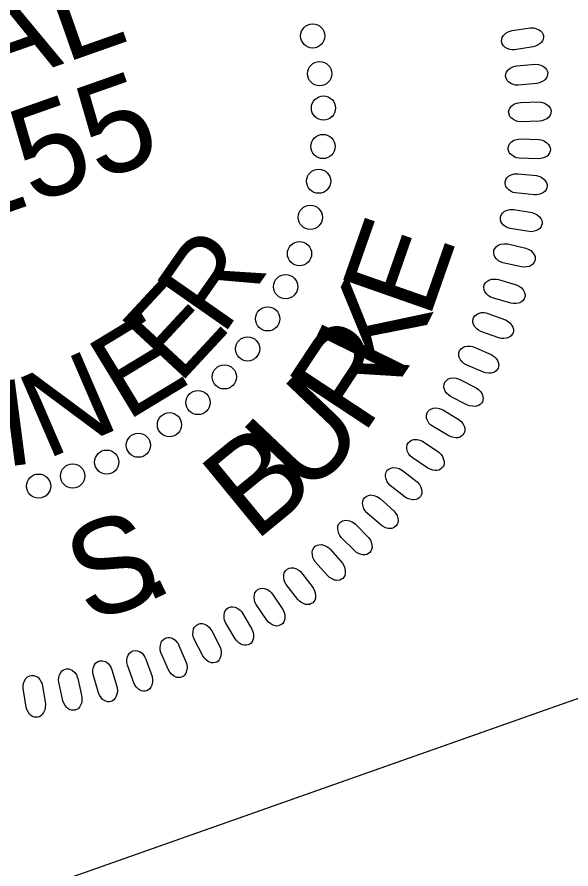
# Model space of a CAD drawing. Extents: x 473817 to 475769, y 501102 to 502694.
# Drawn here: x 475387 to 475423.7, y 502506.6 to 502563 of the extents above; entities that cross this region are included whole.
import ezdxf

# ---------------------------------------------------------------- set-up
doc = ezdxf.new("R2010")
doc.units = 0
for name, color, linetype in [('Sheet PE Seal Cell', 7, 'Continuous'), ('Sheet Plan CELL', 7, 'Continuous'), ('Sheet Sticker Exception Certification CELL', 7, 'Continuous'), ('Sheet Sticker Incomplete CELL', 7, 'Continuous')]:
    doc.layers.add(name, color=color, linetype=linetype)

msp = doc.modelspace()

# ---------------------------------------------------------------- linework, layer by layer
at = {"layer": 'Sheet PE Seal Cell'}
for points in [[(475419.758, 502562.096), (475420.971, 502562.279), (475421.193, 502562.275), (475421.339, 502562.245), (475421.524, 502562.159), (475421.647, 502562.079), (475421.742, 502561.981), (475421.797, 502561.883), (475421.834, 502561.775), (475421.831, 502561.662), (475421.819, 502561.539), (475421.776, 502561.426), (475421.692, 502561.308), (475421.623, 502561.237), (475421.485, 502561.148), (475421.316, 502561.062), (475421.162, 502561.016), (475419.921, 502560.82), (475419.75, 502560.817), (475419.605, 502560.841), (475419.434, 502560.906), (475419.279, 502560.996), (475419.185, 502561.08), (475419.103, 502561.226), (475419.061, 502561.371), (475419.078, 502561.525), (475419.111, 502561.636), (475419.191, 502561.776), (475419.341, 502561.92), (475419.509, 502562.013), (475419.632, 502562.061)], [(475420.069, 502559.768), (475421.291, 502559.875), (475421.512, 502559.856), (475421.656, 502559.817), (475421.835, 502559.72), (475421.952, 502559.633), (475422.042, 502559.527), (475422.09, 502559.427), (475422.12, 502559.317), (475422.11, 502559.204), (475422.091, 502559.082), (475422.041, 502558.973), (475421.95, 502558.86), (475421.876, 502558.793), (475421.732, 502558.713), (475421.559, 502558.638), (475421.402, 502558.601), (475420.151, 502558.484), (475419.98, 502558.492), (475419.837, 502558.525), (475419.67, 502558.6), (475419.522, 502558.7), (475419.434, 502558.789), (475419.36, 502558.941), (475419.327, 502559.088), (475419.354, 502559.24), (475419.395, 502559.349), (475419.483, 502559.484), (475419.641, 502559.618), (475419.815, 502559.701), (475419.941, 502559.741)], [(475420.315, 502557.346), (475421.542, 502557.376), (475421.762, 502557.344), (475421.904, 502557.295), (475422.076, 502557.187), (475422.188, 502557.093), (475422.27, 502556.982), (475422.313, 502556.879), (475422.335, 502556.767), (475422.318, 502556.655), (475422.291, 502556.534), (475422.234, 502556.428), (475422.136, 502556.321), (475422.058, 502556.259), (475421.91, 502556.189), (475421.733, 502556.124), (475421.573, 502556.098), (475420.317, 502556.06), (475420.147, 502556.078), (475420.006, 502556.12), (475419.845, 502556.205), (475419.703, 502556.314), (475419.62, 502556.409), (475419.557, 502556.564), (475419.533, 502556.714), (475419.57, 502556.864), (475419.617, 502556.97), (475419.713, 502557.099), (475419.88, 502557.223), (475420.058, 502557.295), (475420.186, 502557.327)], [(475420.318, 502554.931), (475421.543, 502554.884), (475421.761, 502554.838), (475421.899, 502554.781), (475422.064, 502554.662), (475422.17, 502554.56), (475422.245, 502554.445), (475422.281, 502554.339), (475422.297, 502554.226), (475422.273, 502554.115), (475422.238, 502553.997), (475422.175, 502553.895), (475422.071, 502553.794), (475421.988, 502553.737), (475421.836, 502553.676), (475421.655, 502553.623), (475421.495, 502553.607), (475420.238, 502553.647), (475420.07, 502553.676), (475419.932, 502553.726), (475419.776, 502553.822), (475419.641, 502553.939), (475419.564, 502554.039), (475419.511, 502554.199), (475419.497, 502554.349), (475419.542, 502554.497), (475419.597, 502554.599), (475419.701, 502554.723), (475419.875, 502554.835), (475420.057, 502554.896), (475420.187, 502554.921)], [(475420.152, 502552.627), (475421.372, 502552.503), (475421.587, 502552.443), (475421.721, 502552.378), (475421.878, 502552.249), (475421.978, 502552.141), (475422.046, 502552.022), (475422.075, 502551.914), (475422.083, 502551.8), (475422.052, 502551.691), (475422.009, 502551.575), (475421.94, 502551.476), (475421.83, 502551.382), (475421.745, 502551.331), (475421.589, 502551.279), (475421.405, 502551.238), (475421.243, 502551.232), (475419.993, 502551.351), (475419.826, 502551.39), (475419.691, 502551.449), (475419.542, 502551.555), (475419.415, 502551.68), (475419.345, 502551.785), (475419.301, 502551.947), (475419.296, 502552.098), (475419.351, 502552.242), (475419.412, 502552.342), (475419.524, 502552.458), (475419.704, 502552.56), (475419.89, 502552.609), (475420.021, 502552.625)], [(475419.877, 502550.253), (475421.088, 502550.052), (475421.297, 502549.98), (475421.427, 502549.906), (475421.576, 502549.767), (475421.669, 502549.653), (475421.729, 502549.53), (475421.751, 502549.42), (475421.753, 502549.306), (475421.715, 502549.199), (475421.665, 502549.086), (475421.59, 502548.993), (475421.474, 502548.905), (475421.386, 502548.859), (475421.227, 502548.817), (475421.04, 502548.788), (475420.879, 502548.791), (475419.638, 502548.989), (475419.474, 502549.039), (475419.344, 502549.106), (475419.202, 502549.22), (475419.082, 502549.354), (475419.019, 502549.463), (475418.985, 502549.627), (475418.99, 502549.779), (475419.054, 502549.919), (475419.121, 502550.014), (475419.24, 502550.124), (475419.426, 502550.214), (475419.615, 502550.251), (475419.747, 502550.259)], [(475419.474, 502547.977), (475420.67, 502547.702), (475420.875, 502547.615), (475420.999, 502547.534), (475421.139, 502547.386), (475421.224, 502547.267), (475421.277, 502547.139), (475421.292, 502547.029), (475421.286, 502546.915), (475421.242, 502546.81), (475421.186, 502546.7), (475421.104, 502546.612), (475420.983, 502546.533), (475420.892, 502546.491), (475420.73, 502546.46), (475420.542, 502546.442), (475420.382, 502546.456), (475419.156, 502546.732), (475418.996, 502546.792), (475418.87, 502546.867), (475418.735, 502546.99), (475418.623, 502547.13), (475418.568, 502547.243), (475418.545, 502547.409), (475418.559, 502547.56), (475418.632, 502547.696), (475418.704, 502547.787), (475418.829, 502547.889), (475419.021, 502547.967), (475419.212, 502547.992), (475419.345, 502547.992)], [(475418.861, 502545.624), (475420.037, 502545.273), (475420.236, 502545.175), (475420.355, 502545.086), (475420.486, 502544.929), (475420.563, 502544.805), (475420.608, 502544.674), (475420.616, 502544.563), (475420.603, 502544.45), (475420.552, 502544.348), (475420.489, 502544.242), (475420.402, 502544.159), (475420.276, 502544.088), (475420.183, 502544.052), (475420.02, 502544.03), (475419.831, 502544.025), (475419.671, 502544.048), (475418.466, 502544.4), (475418.309, 502544.47), (475418.189, 502544.553), (475418.061, 502544.684), (475417.959, 502544.832), (475417.91, 502544.948), (475417.898, 502545.116), (475417.922, 502545.264), (475418.002, 502545.396), (475418.08, 502545.482), (475418.212, 502545.576), (475418.408, 502545.642), (475418.6, 502545.655), (475418.732, 502545.647)], [(475418.162, 502543.383), (475419.313, 502542.96), (475419.506, 502542.849), (475419.619, 502542.752), (475419.74, 502542.588), (475419.809, 502542.459), (475419.845, 502542.326), (475419.846, 502542.214), (475419.826, 502542.102), (475419.768, 502542.004), (475419.699, 502541.902), (475419.607, 502541.825), (475419.477, 502541.761), (475419.382, 502541.732), (475419.218, 502541.721), (475419.029, 502541.726), (475418.872, 502541.76), (475417.689, 502542.187), (475417.538, 502542.267), (475417.423, 502542.357), (475417.304, 502542.496), (475417.212, 502542.649), (475417.171, 502542.769), (475417.168, 502542.937), (475417.202, 502543.084), (475417.291, 502543.21), (475417.373, 502543.291), (475417.511, 502543.376), (475417.711, 502543.43), (475417.903, 502543.431), (475418.035, 502543.414)], [(475417.26, 502541.145), (475418.383, 502540.65), (475418.569, 502540.528), (475418.675, 502540.423), (475418.785, 502540.252), (475418.846, 502540.119), (475418.874, 502539.984), (475418.868, 502539.873), (475418.841, 502539.762), (475418.778, 502539.667), (475418.701, 502539.57), (475418.606, 502539.498), (475418.471, 502539.443), (475418.375, 502539.42), (475418.21, 502539.419), (475418.022, 502539.437), (475417.867, 502539.48), (475416.714, 502539.981), (475416.568, 502540.07), (475416.458, 502540.168), (475416.349, 502540.314), (475416.266, 502540.472), (475416.233, 502540.594), (475416.24, 502540.761), (475416.283, 502540.906), (475416.38, 502541.027), (475416.468, 502541.102), (475416.61, 502541.179), (475416.813, 502541.219), (475417.006, 502541.209), (475417.136, 502541.184)], [(475416.303, 502539.012), (475417.393, 502538.447), (475417.57, 502538.313), (475417.67, 502538.202), (475417.769, 502538.025), (475417.822, 502537.888), (475417.841, 502537.751), (475417.828, 502537.64), (475417.794, 502537.531), (475417.725, 502537.441), (475417.643, 502537.349), (475417.543, 502537.283), (475417.405, 502537.236), (475417.307, 502537.22), (475417.143, 502537.229), (475416.956, 502537.259), (475416.804, 502537.312), (475415.685, 502537.884), (475415.545, 502537.982), (475415.442, 502538.086), (475415.341, 502538.239), (475415.269, 502538.402), (475415.243, 502538.526), (475415.262, 502538.693), (475415.313, 502538.834), (475415.417, 502538.948), (475415.51, 502539.018), (475415.657, 502539.086), (475415.862, 502539.114), (475416.053, 502539.091), (475416.181, 502539.058)], [(475415.178, 502536.993), (475416.23, 502536.361), (475416.399, 502536.217), (475416.491, 502536.1), (475416.579, 502535.916), (475416.623, 502535.777), (475416.633, 502535.639), (475416.614, 502535.529), (475416.573, 502535.423), (475416.498, 502535.338), (475416.411, 502535.25), (475416.306, 502535.191), (475416.166, 502535.153), (475416.067, 502535.142), (475415.904, 502535.161), (475415.719, 502535.203), (475415.571, 502535.266), (475414.491, 502535.906), (475414.357, 502536.013), (475414.26, 502536.124), (475414.17, 502536.282), (475414.107, 502536.45), (475414.089, 502536.575), (475414.119, 502536.74), (475414.178, 502536.879), (475414.29, 502536.986), (475414.387, 502537.051), (475414.538, 502537.108), (475414.744, 502537.123), (475414.933, 502537.088), (475415.06, 502537.047)], [(475413.901, 502534.882), (475414.91, 502534.186), (475415.069, 502534.031), (475415.156, 502533.909), (475415.231, 502533.72), (475415.266, 502533.577), (475415.269, 502533.44), (475415.242, 502533.331), (475415.194, 502533.228), (475415.114, 502533.147), (475415.022, 502533.066), (475414.914, 502533.013), (475414.771, 502532.984), (475414.672, 502532.979), (475414.51, 502533.009), (475414.329, 502533.062), (475414.185, 502533.134), (475413.146, 502533.841), (475413.019, 502533.956), (475412.931, 502534.073), (475412.849, 502534.237), (475412.798, 502534.408), (475412.788, 502534.534), (475412.827, 502534.697), (475412.896, 502534.831), (475413.014, 502534.932), (475413.114, 502534.989), (475413.268, 502535.038), (475413.475, 502535.04), (475413.663, 502534.993), (475413.785, 502534.944)], [(475412.509, 502532.983), (475413.473, 502532.225), (475413.622, 502532.06), (475413.7, 502531.933), (475413.764, 502531.739), (475413.79, 502531.595), (475413.783, 502531.458), (475413.751, 502531.351), (475413.696, 502531.25), (475413.611, 502531.175), (475413.514, 502531.099), (475413.403, 502531.054), (475413.259, 502531.033), (475413.16, 502531.035), (475413, 502531.075), (475412.822, 502531.139), (475412.683, 502531.22), (475411.691, 502531.991), (475411.572, 502532.114), (475411.49, 502532.235), (475411.42, 502532.405), (475411.379, 502532.579), (475411.377, 502532.705), (475411.426, 502532.865), (475411.504, 502532.995), (475411.627, 502533.088), (475411.731, 502533.139), (475411.888, 502533.178), (475412.095, 502533.166), (475412.278, 502533.109), (475412.398, 502533.052)], [(475411.023, 502531.128), (475411.937, 502530.31), (475412.076, 502530.136), (475412.145, 502530.004), (475412.197, 502529.807), (475412.214, 502529.662), (475412.199, 502529.525), (475412.159, 502529.42), (475412.099, 502529.323), (475412.01, 502529.253), (475411.907, 502529.184), (475411.793, 502529.146), (475411.649, 502529.135), (475411.55, 502529.143), (475411.393, 502529.192), (475411.219, 502529.268), (475411.086, 502529.357), (475410.144, 502530.189), (475410.032, 502530.319), (475409.958, 502530.446), (475409.899, 502530.618), (475409.869, 502530.795), (475409.875, 502530.921), (475409.935, 502531.078), (475410.02, 502531.203), (475410.149, 502531.287), (475410.256, 502531.332), (475410.415, 502531.361), (475410.621, 502531.336), (475410.8, 502531.267), (475410.916, 502531.203)], [(475409.394, 502529.426), (475410.256, 502528.552), (475410.383, 502528.37), (475410.444, 502528.234), (475410.484, 502528.034), (475410.491, 502527.888), (475410.467, 502527.752), (475410.421, 502527.65), (475410.354, 502527.557), (475410.261, 502527.494), (475410.155, 502527.431), (475410.039, 502527.399), (475409.894, 502527.397), (475409.795, 502527.411), (475409.643, 502527.471), (475409.474, 502527.557), (475409.346, 502527.654), (475408.458, 502528.544), (475408.355, 502528.681), (475408.289, 502528.812), (475408.241, 502528.988), (475408.223, 502529.166), (475408.236, 502529.291), (475408.305, 502529.444), (475408.398, 502529.563), (475408.533, 502529.64), (475408.642, 502529.677), (475408.802, 502529.696), (475409.006, 502529.659), (475409.181, 502529.579), (475409.293, 502529.507)], [(475407.723, 502527.768), (475408.527, 502526.842), (475408.643, 502526.652), (475408.695, 502526.513), (475408.722, 502526.311), (475408.72, 502526.165), (475408.688, 502526.031), (475408.636, 502525.932), (475408.564, 502525.843), (475408.466, 502525.785), (475408.356, 502525.729), (475408.238, 502525.705), (475408.094, 502525.712), (475407.996, 502525.733), (475407.847, 502525.802), (475407.685, 502525.898), (475407.563, 502526.004), (475406.733, 502526.947), (475406.638, 502527.09), (475406.581, 502527.225), (475406.543, 502527.404), (475406.537, 502527.583), (475406.558, 502527.707), (475406.636, 502527.855), (475406.737, 502527.969), (475406.875, 502528.036), (475406.988, 502528.067), (475407.148, 502528.075), (475407.349, 502528.026), (475407.519, 502527.935), (475407.625, 502527.856)], [(475405.846, 502526.196), (475406.591, 502525.221), (475406.695, 502525.025), (475406.739, 502524.882), (475406.753, 502524.679), (475406.742, 502524.533), (475406.701, 502524.401), (475406.642, 502524.306), (475406.564, 502524.222), (475406.464, 502524.17), (475406.351, 502524.121), (475406.232, 502524.105), (475406.088, 502524.121), (475405.992, 502524.148), (475405.847, 502524.226), (475405.691, 502524.332), (475405.576, 502524.445), (475404.807, 502525.439), (475404.722, 502525.587), (475404.673, 502525.725), (475404.647, 502525.906), (475404.651, 502526.085), (475404.68, 502526.208), (475404.768, 502526.351), (475404.875, 502526.457), (475405.017, 502526.516), (475405.132, 502526.54), (475405.293, 502526.539), (475405.49, 502526.476), (475405.653, 502526.374), (475405.756, 502526.29)], [(475403.908, 502524.801), (475404.591, 502523.781), (475404.681, 502523.578), (475404.716, 502523.433), (475404.717, 502523.23), (475404.698, 502523.084), (475404.649, 502522.956), (475404.584, 502522.864), (475404.501, 502522.786), (475404.398, 502522.74), (475404.281, 502522.698), (475404.161, 502522.689), (475404.019, 502522.714), (475403.925, 502522.747), (475403.785, 502522.834), (475403.636, 502522.95), (475403.529, 502523.07), (475402.823, 502524.11), (475402.748, 502524.264), (475402.707, 502524.404), (475402.693, 502524.587), (475402.708, 502524.765), (475402.745, 502524.886), (475402.842, 502525.022), (475402.955, 502525.123), (475403.102, 502525.172), (475403.217, 502525.189), (475403.377, 502525.178), (475403.571, 502525.102), (475403.727, 502524.991), (475403.824, 502524.9)], [(475401.931, 502523.533), (475402.548, 502522.472), (475402.627, 502522.265), (475402.652, 502522.118), (475402.64, 502521.915), (475402.611, 502521.771), (475402.554, 502521.645), (475402.484, 502521.558), (475402.397, 502521.485), (475402.29, 502521.446), (475402.172, 502521.411), (475402.051, 502521.41), (475401.911, 502521.444), (475401.819, 502521.483), (475401.686, 502521.579), (475401.543, 502521.703), (475401.443, 502521.83), (475400.805, 502522.912), (475400.739, 502523.069), (475400.708, 502523.214), (475400.705, 502523.396), (475400.731, 502523.573), (475400.775, 502523.691), (475400.881, 502523.822), (475401, 502523.914), (475401.149, 502523.954), (475401.265, 502523.964), (475401.425, 502523.942), (475401.613, 502523.856), (475401.763, 502523.734), (475401.853, 502523.638)], [(475399.884, 502522.376), (475400.434, 502521.279), (475400.499, 502521.067), (475400.515, 502520.918), (475400.49, 502520.716), (475400.453, 502520.575), (475400.388, 502520.453), (475400.313, 502520.371), (475400.221, 502520.302), (475400.112, 502520.271), (475399.991, 502520.243), (475399.871, 502520.25), (475399.733, 502520.292), (475399.644, 502520.337), (475399.516, 502520.441), (475399.382, 502520.574), (475399.291, 502520.707), (475398.721, 502521.827), (475398.666, 502521.989), (475398.644, 502522.134), (475398.653, 502522.316), (475398.689, 502522.491), (475398.741, 502522.607), (475398.854, 502522.73), (475398.98, 502522.815), (475399.131, 502522.846), (475399.247, 502522.848), (475399.405, 502522.816), (475399.587, 502522.718), (475399.729, 502522.587), (475399.813, 502522.485)], [(475397.718, 502521.407), (475398.197, 502520.277), (475398.249, 502520.061), (475398.256, 502519.912), (475398.218, 502519.712), (475398.172, 502519.573), (475398.099, 502519.456), (475398.019, 502519.379), (475397.923, 502519.316), (475397.813, 502519.291), (475397.691, 502519.272), (475397.571, 502519.286), (475397.435, 502519.337), (475397.349, 502519.387), (475397.229, 502519.498), (475397.104, 502519.64), (475397.021, 502519.778), (475396.523, 502520.932), (475396.477, 502521.097), (475396.464, 502521.243), (475396.485, 502521.425), (475396.533, 502521.597), (475396.592, 502521.708), (475396.712, 502521.825), (475396.843, 502521.902), (475396.995, 502521.923), (475397.111, 502521.918), (475397.267, 502521.877), (475397.444, 502521.767), (475397.576, 502521.628), (475397.654, 502521.52)], [(475395.526, 502520.504), (475395.934, 502519.347), (475395.971, 502519.128), (475395.969, 502518.978), (475395.919, 502518.781), (475395.864, 502518.645), (475395.784, 502518.533), (475395.7, 502518.461), (475395.6, 502518.405), (475395.488, 502518.386), (475395.365, 502518.375), (475395.246, 502518.396), (475395.114, 502518.456), (475395.031, 502518.511), (475394.918, 502518.63), (475394.802, 502518.779), (475394.728, 502518.922), (475394.304, 502520.105), (475394.269, 502520.272), (475394.265, 502520.419), (475394.296, 502520.599), (475394.355, 502520.768), (475394.421, 502520.876), (475394.549, 502520.984), (475394.684, 502521.053), (475394.838, 502521.065), (475394.953, 502521.053), (475395.106, 502521.001), (475395.274, 502520.881), (475395.398, 502520.733), (475395.469, 502520.621)], [(475393.283, 502519.789), (475393.617, 502518.609), (475393.641, 502518.388), (475393.629, 502518.239), (475393.567, 502518.045), (475393.504, 502517.913), (475393.418, 502517.806), (475393.328, 502517.739), (475393.224, 502517.689), (475393.112, 502517.679), (475392.989, 502517.674), (475392.872, 502517.703), (475392.744, 502517.771), (475392.664, 502517.831), (475392.559, 502517.957), (475392.452, 502518.113), (475392.387, 502518.261), (475392.038, 502519.468), (475392.013, 502519.637), (475392.019, 502519.784), (475392.062, 502519.961), (475392.131, 502520.127), (475392.203, 502520.23), (475392.338, 502520.33), (475392.476, 502520.39), (475392.631, 502520.392), (475392.745, 502520.372), (475392.895, 502520.312), (475393.056, 502520.181), (475393.17, 502520.026), (475393.233, 502519.91)], [(475388.692, 502518.726), (475388.876, 502517.512), (475388.872, 502517.29), (475388.841, 502517.144), (475388.755, 502516.96), (475388.675, 502516.837), (475388.577, 502516.741), (475388.479, 502516.686), (475388.371, 502516.65), (475388.258, 502516.653), (475388.135, 502516.664), (475388.022, 502516.708), (475387.904, 502516.791), (475387.833, 502516.861), (475387.744, 502516.998), (475387.658, 502517.167), (475387.612, 502517.322), (475387.417, 502518.563), (475387.413, 502518.734), (475387.437, 502518.879), (475387.502, 502519.05), (475387.592, 502519.204), (475387.676, 502519.298), (475387.822, 502519.38), (475387.968, 502519.423), (475388.121, 502519.405), (475388.232, 502519.372), (475388.372, 502519.293), (475388.515, 502519.143), (475388.609, 502518.975), (475388.658, 502518.852)], [(475391.032, 502519.205), (475391.291, 502518.006), (475391.301, 502517.784), (475391.28, 502517.636), (475391.206, 502517.446), (475391.134, 502517.319), (475391.041, 502517.217), (475390.948, 502517.156), (475390.842, 502517.113), (475390.729, 502517.109), (475390.605, 502517.112), (475390.49, 502517.148), (475390.367, 502517.225), (475390.291, 502517.29), (475390.194, 502517.422), (475390.098, 502517.584), (475390.042, 502517.736), (475389.769, 502518.962), (475389.755, 502519.132), (475389.77, 502519.279), (475389.823, 502519.453), (475389.903, 502519.614), (475389.982, 502519.712), (475390.122, 502519.804), (475390.265, 502519.855), (475390.419, 502519.847), (475390.532, 502519.821), (475390.677, 502519.751), (475390.829, 502519.61), (475390.934, 502519.448), (475390.99, 502519.328)]]:
    msp.add_lwpolyline(points, close=True, dxfattribs=at)
for centre in [(475406.567, 502561.747), (475407.026, 502559.247), (475407.279, 502556.971), (475407.247, 502554.426), (475406.958, 502552.128), (475406.407, 502549.738), (475405.693, 502547.332), (475404.773, 502545.149), (475403.586, 502543.017), (475402.26, 502541.03), (475400.717, 502539.177), (475398.976, 502537.479), (475397.087, 502536.011), (475395.033, 502534.654), (475392.936, 502533.535), (475390.685, 502532.616), (475388.43, 502531.948)]:
    msp.add_circle(centre, 0.801, dxfattribs=at)
at = {"layer": 'Sheet Plan CELL'}
msp.add_lwpolyline([(475314.805, 502598.626), (475409.098, 502631.888), (475446.525, 502525.783), (475352.22, 502492.517)], close=True, dxfattribs=at)
at = {"layer": 'Sheet Sticker Exception Certification CELL'}
msp.add_line((475257.868, 502459.274), (475446.521, 502525.794), dxfattribs=at)
msp.add_line((475257.868, 502459.274), (475446.521, 502525.794), dxfattribs=at)

# ---------------------------------------------------------------- texts
at = {"layer": 'Sheet PE Seal Cell'}
for s, height, rotation, p in [('SEAL', 6.2363, 19.4044, (475374.413, 502554.389)), ('46155', 6.2363, 19.4044, (475374.885, 502545.989)), ('E', 6.236, 70.6913, (475414.242, 502542.891)), ('R', 5.669, 55.0866, (475400.593, 502541.817)), ('K', 6.236, 63.8456, (475412.152, 502538.576)), ('E', 5.669, 47.1468, (475397.713, 502538.615)), ('E', 5.669, 31.2672, (475394.248, 502536.202)), ('R', 6.236, 56.5706, (475409.9, 502535.245)), ('N', 5.669, 23.3274, (475388.934, 502533.685)), ('U', 6.236, 46.4707, (475406.163, 502531.099)), ('I', 5.669, 7.4478, (475386.18, 502533.215)), ('B', 6.236, 39.3539, (475402.709, 502528.204)), ('S', 6.236, 18.8056, (475391.651, 502522.876)), ('.', 6.236, 25.6513, (475395.476, 502524.174))]:
    msp.add_text(s, height=height, rotation=rotation, dxfattribs=at).set_placement(p)
at = {"layer": 'Sheet Sticker Incomplete CELL'}
for s, height, p in [('INCOMPLETE PLANS', 11.52, (475268.744, 502535.146)), ('DO NOT USE FOR R/W ACQUISITION', 5.76, (475274.12, 502529.672))]:
    msp.add_text(s, height=height, rotation=19.423, dxfattribs=at).set_placement(p)

doc.saveas('drawing.dxf')
